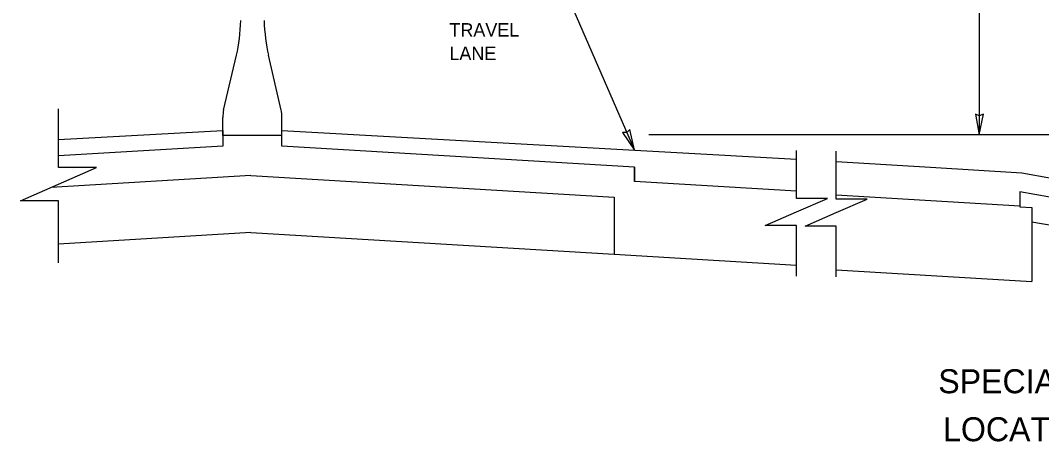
# Model space of a CAD drawing. Extents: x 57428 to 58066, y 11696 to 12105.
# Drawn here: x 57711.6 to 57924.4, y 11709 to 11796.7 of the extents above; entities that cross this region are included whole.
import ezdxf

# ---------------------------------------------------------------- set-up
doc = ezdxf.new("R2010")
doc.units = 0
for name, color, linetype in [('52', 7, 'Continuous'), ('Default', 7, 'Continuous'), ('DimLines_dp', 7, 'Continuous'), ('SheetLines_dp', 7, 'Continuous'), ('XSGrdLine_ex', 7, 'Continuous')]:
    doc.layers.add(name, color=color, linetype=linetype)

msp = doc.modelspace()

# ---------------------------------------------------------------- linework, layer by layer
at = {"layer": '52'}
msp.add_line((57985.74, 11772.84), (57842.57, 11772.84), dxfattribs=at)
at = {"layer": 'Default'}
for points in [[(57719.56, 11746.2), (57719.56, 11759.14), (57711.65, 11759.14), (57719.56, 11762.59), (57727.48, 11766.04), (57719.56, 11766.04), (57719.56, 11778.29)], [(57873.33, 11743.42), (57873.33, 11753.98), (57866.86, 11753.98), (57873.33, 11756.79), (57879.79, 11759.6), (57873.33, 11759.6), (57873.33, 11769.6)], [(57881.63, 11743.28), (57881.63, 11753.84), (57875.17, 11753.84), (57881.63, 11756.66), (57888.09, 11759.47), (57881.63, 11759.47), (57881.63, 11769.47)]]:
    msp.add_lwpolyline(points, dxfattribs=at)
at = {"layer": 'DimLines_dp'}
for p, q in [((57911.45, 11858.7), (57911.45, 11772.84)), ((57826.29, 11800.28), (57839.61, 11769.66)), ((57911.45, 11776.86), (57910.64, 11777.19)), ((57910.64, 11777.19), (57911.45, 11772.84)), ((57911.45, 11772.84), (57912.29, 11777.19)), ((57912.29, 11777.19), (57911.45, 11776.86)), ((57838, 11773.35), (57837.13, 11773.33)), ((57837.13, 11773.33), (57839.61, 11769.66)), ((57838.64, 11773.99), (57838, 11773.35)), ((57839.61, 11769.66), (57838.64, 11773.99))]:
    msp.add_line(p, q, dxfattribs=at)
at = {"layer": 'XSGrdLine_ex'}
for p, q in [((57753.99, 11778.04), (57756.66, 11789.49)), ((57765.99, 11778.04), (57763.32, 11789.49)), ((57753.83, 11772.72), (57753.83, 11776.5)), ((57766.15, 11772.72), (57766.15, 11776.5)), ((57719.56, 11771.88), (57753.83, 11773.79)), ((57753.83, 11773.79), (57753.83, 11770.54)), ((57766.15, 11773.76), (57873.33, 11767.78)), ((57766.15, 11770.5), (57766.15, 11773.76)), ((57766.15, 11770.5), (57766.15, 11773.76)), ((57766.15, 11772.72), (57753.83, 11772.72)), ((57753.83, 11772.72), (57753.83, 11770.54)), ((57753.83, 11770.54), (57719.56, 11768.48)), ((57839.61, 11766.1), (57766.15, 11770.5)), ((57881.63, 11767.28), (57901.31, 11766.1)), ((57759.69, 11764.42), (57718.03, 11761.92)), ((57759.69, 11764.42), (57835.36, 11759.88)), ((57839.61, 11763.14), (57839.61, 11766.1)), ((57839.61, 11766.1), (57839.61, 11763.14)), ((57901.31, 11766.1), (57920.31, 11764.96)), ((57920.31, 11764.96), (57926.48, 11763.85)), ((57873.33, 11761.14), (57839.61, 11763.14)), ((57919.9, 11758), (57881.63, 11760.27)), ((57991.17, 11748.2), (57919.9, 11761.02)), ((57919.9, 11761.02), (57919.9, 11757.87)), ((57835.36, 11759.88), (57835.36, 11747.99)), ((57919.9, 11757.87), (57922.37, 11757.72)), ((57922.37, 11757.72), (57922.37, 11742.32)), ((57922.37, 11754.76), (57991.17, 11742.38)), ((57759.69, 11752.53), (57719.56, 11750.12)), ((57759.69, 11752.53), (57835.36, 11747.99)), ((57835.36, 11747.99), (57873.33, 11745.71)), ((57881.63, 11744.76), (57922.37, 11742.32))]:
    msp.add_line(p, q, dxfattribs=at)
for centre, major_axis, start_param, end_param in [((57752.46, 11798.32), (0, -15.4), 0.96007, 1.465919), ((57767.53, 11798.32), (0, -15.4), 4.817266, 5.323115), ((57754.73, 11776.5), (0, 2.7), 0.96007, 1.570796), ((57765.25, 11776.5), (0, 2.7), 4.712389, 5.323115)]:
    msp.add_ellipse(centre, major_axis=major_axis, ratio=0.333333, start_param=start_param, end_param=end_param, dxfattribs=at)

# ---------------------------------------------------------------- texts
at = {"layer": 'DimLines_dp'}
for s, p in [('TRAVEL ', (57801.03, 11793.34)), ('LANE', (57801.03, 11788.44))]:
    msp.add_text(s, height=2.8, dxfattribs=at).set_placement(p)
at = {"layer": 'SheetLines_dp'}
for s, p in [('SPECIAL DESIGN MILEPOST ', (57902.9, 11719.02)), (' LOCATION AND MOUNTING  ', (57902.04, 11709.02))]:
    msp.add_text(s, height=5, rotation=360, dxfattribs=at).set_placement(p)

doc.saveas('drawing.dxf')
